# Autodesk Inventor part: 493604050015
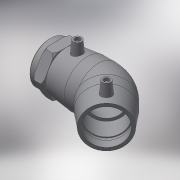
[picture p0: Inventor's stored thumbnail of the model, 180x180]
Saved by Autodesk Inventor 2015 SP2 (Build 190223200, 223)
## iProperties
Created: 2017-06
Part Number: 493604050015
Material: Generic
Description: PLASSON 45° ELBOW TRANSITION FEMALE 50-1.1/2"
Document SubType Name: Modeling
Designer: KIM
Mass: 261.441 g
Surface Area: 609.178 cm^2
Volume: 261.441 cm^3
Density: 1 g/cm^3
Appearance: Default
Author: KIM
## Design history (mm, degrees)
derived "493604.ipt"
feature "Solid1::493604.ipt"
tag "TaggingFeature1"
body "Solid1"
other parameters: "d2" = 67, "d4" = 31.25, "d5" = 60.3, "d8" = 168 deg, "d10" = 19.6, "d11" = 6.53333, "d29" = 51, "d30" = 15, "d31" = 43.75, "d34" = 5 deg, "d41" = 4, "d42" = 14, "d43" = 0, "d50" = 42.5, "d51" = 19.6, "d52" = 49, "d54" = 135 deg, "d86" = 30.15, "d87" = 135 deg, "d88" = 125, "d90" = 49, "d91" = 0, "d92" = 49, "d93" = 0, "d101" = 3, "d102" = 0, "d107" = 0.1, "d108" = 38, "d110" = 25, "d112" = 60.3, "d113" = 44.845, "d114" = 22.5, "d128" = 15, "d129" = 0, "d132" = 2.5, "d133" = 45 deg, "d134" = 45 deg, "d136" = 1.5, "L_1" = 49, "D_" = 38, "A_" = 51, "d_2" = 12, "L_2" = 25, "Rp_" = 44.845, "D_1" = 67
